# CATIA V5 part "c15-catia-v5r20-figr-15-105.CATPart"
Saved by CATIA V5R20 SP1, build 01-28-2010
Part number: Part1
Bounding box of the stored display mesh (mm): x -55.37 to 68.649, y -21.457 to 35.984, z 0 to 57.441
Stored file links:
  D:\v5_r20\psrt_files_downloaded\c15\c15-catia-v5r20-figr-15-105.CATPart
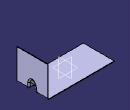
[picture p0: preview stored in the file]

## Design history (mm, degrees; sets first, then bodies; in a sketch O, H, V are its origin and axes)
SheetMetalParameters1: Thickness 1, BendRadius 2, KFactor 0.400515 {= log(min(100,max(20*SheetMetalParameters1.BendRadius,SheetMetalParameters1.Thickness)/SheetMetalParameters1.Thickness))/log(100)/2}, ReliefRadialLength 1, ReliefAxialLength 2, MinimumBendRadius 0
Body1 (main body)
  Sketch1 on xy-plane, origin (0, 0, 0), H (1, 0, 0), V (0, 1, 0)
    line L1 (-55.3695, 35.9836) -> (67.649, 35.9836)
    line L2 (67.649, 35.9836) -> (67.649, -21.4575)
    line L3 (67.649, -21.4575) -> (-55.3695, -21.4575)
    line L4 (-55.3695, -21.4575) -> (-55.3695, 35.9836)
    horizontal: L1 H, L3 H
    vertical: L2 V, L4 V
  Wall1: Thickness 1, Profile Sketch1
  d_NewWallOnEdge1: NewWallOnEdge_Edge edge [face of Wall1 | face of Wall1], NewWallOnEdge_Length 57.4411, NewWallOnEdge_HeightLimitOffset 0, NewWallOnEdge_WidthOffset1 0, NewWallOnEdge_WidthOffset2 0, NewWallOnEdge_Angle 90, NewWallOnEdge_BendRadiusValue 2 {= SheetMetalParameters1.BendRadius}, NewWallOnEdge_BendTable SheetMetalParameters1, KFacteur 0.400515 {= log(min(100,max(20*d_NewWallOnEdge1.Radius,SheetMetalParameters1.Thickness)/SheetMetalParameters1.Thickness))/log(100)/2}
  Sketch2 on , origin (67.7759, 6.9809, 0.8843), H (0.7052, 0, 0.709), V (0, -1, 0)
    point P1 (0, 0)
  d_Stamp1: Stamp_FilletRadius 2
